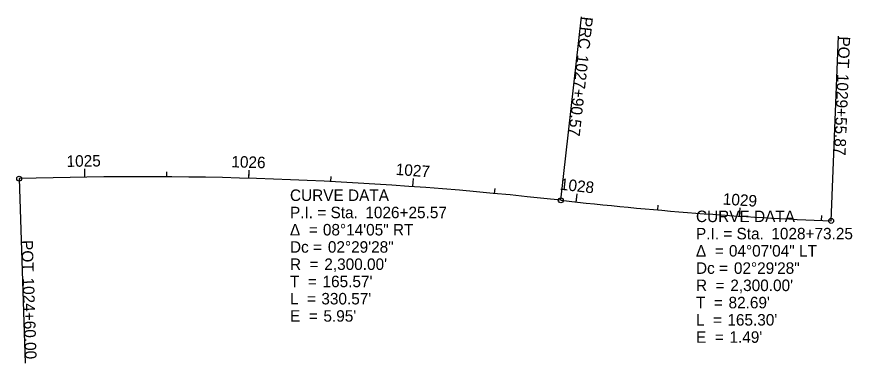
# Model space of a CAD drawing. Extents: x 2192966 to 2197975, y 660343 to 661858.
# Drawn here: x 2197466 to 2197975, y 661647 to 661858 of the extents above; entities that cross this region are included whole.
import ezdxf

# ---------------------------------------------------------------- set-up
doc = ezdxf.new("R2010")
doc.units = 0
for name, color, linetype in [('PM_X_Cells', 7, 'Continuous'), ('PM_X_CL_Double_Solid', 7, 'Continuous'), ('PM_X_Crosswalk', 7, 'Continuous'), ('PM_X_Dotted_Line', 7, 'Continuous'), ('PM_X_Edge_Line', 7, 'Continuous'), ('PM_X_Stop_Line', 7, 'Continuous'), ('PM_X_Yield_Line', 7, 'Continuous')]:
    doc.layers.add(name, color=color, linetype=linetype)

msp = doc.modelspace()

# ---------------------------------------------------------------- linework, layer by layer
at = {"layer": 'PM_X_Cells'}
for p, q in [((2197797.82, 661746.67), (2197810.38, 661858.46)), ((2197962.6, 661734.13), (2197967.1, 661846.54)), ((2197507.79, 661760.81), (2197507.74, 661763.81)), ((2197467.8, 661759.88), (2197471.38, 661647.44))]:
    msp.add_line(p, q, dxfattribs=at)
for centre in [(2197467.8, 661759.88), (2197797.82, 661746.67), (2197962.6, 661734.13)]:
    msp.add_circle(centre, 1.5, dxfattribs=at)
at = {"layer": 'PM_X_CL_Double_Solid'}
for p, q in [((2197797.82, 661746.67), (2197810.38, 661858.46)), ((2197962.6, 661734.13), (2197967.1, 661846.54)), ((2197507.79, 661760.81), (2197507.71, 661765.81)), ((2197607.78, 661760.08), (2197607.86, 661763.08)), ((2197467.8, 661759.88), (2197471.38, 661647.44)), ((2197707.64, 661755), (2197707.86, 661758)), ((2197807.19, 661745.63), (2197807.51, 661748.62)), ((2197906.81, 661737.04), (2197907.01, 661740.04))]:
    msp.add_line(p, q, dxfattribs=at)
for centre in [(2197467.8, 661759.88), (2197797.82, 661746.67), (2197962.6, 661734.13)]:
    msp.add_circle(centre, 1.5, dxfattribs=at)
at = {"layer": 'PM_X_Edge_Line'}
for centre, start, end in [((2197541.04, 659461.05), 83.58998, 91.82483), ((2198054.59, 664032.29), 263.58998, 267.7078)]:
    msp.add_arc(centre, 2300, start, end, dxfattribs=at)
at = {"layer": 'PM_X_Yield_Line'}
for p, q in [((2197797.82, 661746.67), (2197810.38, 661858.46)), ((2197962.6, 661734.13), (2197967.1, 661846.54)), ((2197507.79, 661760.81), (2197507.71, 661765.81)), ((2197557.78, 661760.99), (2197557.81, 661763.99)), ((2197607.78, 661760.08), (2197607.92, 661765.08)), ((2197657.73, 661758.08), (2197657.89, 661761.08)), ((2197467.8, 661759.88), (2197471.38, 661647.44)), ((2197707.64, 661755), (2197708, 661759.99)), ((2197757.46, 661750.84), (2197757.75, 661753.83)), ((2197807.19, 661745.63), (2197807.73, 661750.61)), ((2197856.96, 661740.8), (2197857.21, 661743.79)), ((2197906.81, 661737.04), (2197907.13, 661742.03)), ((2197956.74, 661734.37), (2197956.87, 661737.37))]:
    msp.add_line(p, q, dxfattribs=at)
for centre in [(2197467.8, 661759.88), (2197797.82, 661746.67), (2197962.6, 661734.13)]:
    msp.add_circle(centre, 1.5, dxfattribs=at)

# ---------------------------------------------------------------- texts
at = {"layer": 'PM_X_Cells'}
for s, rotation, p in [('PRC', 263.59, (2197810.53, 661858.79)), ('POT', 267.7078, (2197967.22, 661846.6)), ('1027+90.57', 263.59, (2197807.92, 661835.56)), ('1029+55.87', 267.7078, (2197966.31, 661823.79)), ('POT', 271.8248, (2197469.11, 661722.32)), ('1024+60.00', 271.8248, (2197469.84, 661699.51))]:
    msp.add_text(s, height=7, rotation=rotation, dxfattribs=at).set_placement(p)
at = {"layer": 'PM_X_CL_Double_Solid'}
for s, rotation, p in [('PRC', 263.59, (2197810.53, 661858.79)), ('POT', 267.7078, (2197967.22, 661846.6)), ('1027+90.57', 263.59, (2197807.92, 661835.56)), ('1029+55.87', 267.7078, (2197966.31, 661823.79)), ('1025', 0.8284, (2197496.74, 661767.01)), ('POT', 271.8248, (2197469.11, 661722.32)), ('1024+60.00', 271.8248, (2197469.84, 661699.51))]:
    msp.add_text(s, height=7, rotation=rotation, dxfattribs=at).set_placement(p)
at = {"layer": 'PM_X_Crosswalk'}
for s, p in [('CURVE DATA', (2197632.81, 661746.27)), ('P.I. = Sta. ', (2197632.81, 661735.77)), ('1026+25.57', (2197678.73, 661735.77)), ('CURVE DATA', (2197880.21, 661733.4)), ('Δ  = ', (2197632.81, 661725.27)), ('08°14\'05" RT', (2197652.86, 661725.27)), ('P.I. = Sta. ', (2197880.21, 661722.9)), ('1028+73.25', (2197926.13, 661722.9)), ('Dc = ', (2197632.81, 661714.77)), ('02°29\'28"', (2197655.9, 661714.77)), ('04°07\'04" LT', (2197900.27, 661712.4)), ('Δ  = ', (2197880.21, 661712.4)), ('R  = ', (2197632.81, 661704.27)), ("2,300.00'", (2197653.73, 661704.27)), ('Dc = ', (2197880.21, 661701.9)), ('02°29\'28"', (2197903.31, 661701.9)), ('T  = ', (2197632.81, 661693.77)), ("165.57'", (2197652.64, 661693.77)), ('R  = ', (2197880.21, 661691.4)), ("2,300.00'", (2197901.13, 661691.4)), ('L  = ', (2197632.81, 661683.27)), ("330.57'", (2197651.92, 661683.27)), ('T  = ', (2197880.21, 661680.9)), ("82.69'", (2197900.04, 661680.9)), ('E  = ', (2197632.81, 661672.77)), ("5.95'", (2197653.19, 661672.77)), ('L  = ', (2197880.21, 661670.4)), ("165.30'", (2197899.33, 661670.4)), ('E  = ', (2197880.21, 661659.9)), ("1.49'", (2197900.59, 661659.9))]:
    msp.add_text(s, height=7, dxfattribs=at).set_placement(p)
at = {"layer": 'PM_X_Dotted_Line'}
for s, p in [('CURVE DATA', (2197632.81, 661746.27)), ('P.I. = Sta. ', (2197632.81, 661735.77)), ('1026+25.57', (2197678.73, 661735.77)), ('CURVE DATA', (2197880.21, 661733.4)), ('Δ  = ', (2197632.81, 661725.27)), ('08°14\'05" RT', (2197652.86, 661725.27)), ('P.I. = Sta. ', (2197880.21, 661722.9)), ('1028+73.25', (2197926.13, 661722.9)), ('Dc = ', (2197632.81, 661714.77)), ('02°29\'28"', (2197655.9, 661714.77)), ('04°07\'04" LT', (2197900.27, 661712.4)), ('Δ  = ', (2197880.21, 661712.4)), ('R  = ', (2197632.81, 661704.27)), ("2,300.00'", (2197653.73, 661704.27)), ('Dc = ', (2197880.21, 661701.9)), ('02°29\'28"', (2197903.31, 661701.9)), ('T  = ', (2197632.81, 661693.77)), ("165.57'", (2197652.64, 661693.77)), ('R  = ', (2197880.21, 661691.4)), ("2,300.00'", (2197901.13, 661691.4)), ('L  = ', (2197632.81, 661683.27)), ("330.57'", (2197651.92, 661683.27)), ('T  = ', (2197880.21, 661680.9)), ("82.69'", (2197900.04, 661680.9)), ('E  = ', (2197632.81, 661672.77)), ("5.95'", (2197653.19, 661672.77)), ('L  = ', (2197880.21, 661670.4)), ("165.30'", (2197899.33, 661670.4)), ('E  = ', (2197880.21, 661659.9)), ("1.49'", (2197900.59, 661659.9))]:
    msp.add_text(s, height=7, dxfattribs=at).set_placement(p)
at = {"layer": 'PM_X_Stop_Line'}
for s, p in [('CURVE DATA', (2197632.81, 661746.27)), ('P.I. = Sta. ', (2197632.81, 661735.77)), ('1026+25.57', (2197678.73, 661735.77)), ('CURVE DATA', (2197880.21, 661733.4)), ('Δ  = ', (2197632.81, 661725.27)), ('08°14\'05" RT', (2197652.86, 661725.27)), ('P.I. = Sta. ', (2197880.21, 661722.9)), ('1028+73.25', (2197926.13, 661722.9)), ('Dc = ', (2197632.81, 661714.77)), ('02°29\'28"', (2197655.9, 661714.77)), ('04°07\'04" LT', (2197900.27, 661712.4)), ('Δ  = ', (2197880.21, 661712.4)), ('R  = ', (2197632.81, 661704.27)), ("2,300.00'", (2197653.73, 661704.27)), ('Dc = ', (2197880.21, 661701.9)), ('02°29\'28"', (2197903.31, 661701.9)), ('T  = ', (2197632.81, 661693.77)), ("165.57'", (2197652.64, 661693.77)), ('R  = ', (2197880.21, 661691.4)), ("2,300.00'", (2197901.13, 661691.4)), ('L  = ', (2197632.81, 661683.27)), ("330.57'", (2197651.92, 661683.27)), ('T  = ', (2197880.21, 661680.9)), ("82.69'", (2197900.04, 661680.9)), ('E  = ', (2197632.81, 661672.77)), ("5.95'", (2197653.19, 661672.77)), ('L  = ', (2197880.21, 661670.4)), ("165.30'", (2197899.33, 661670.4)), ('E  = ', (2197880.21, 661659.9)), ("1.49'", (2197900.59, 661659.9))]:
    msp.add_text(s, height=7, dxfattribs=at).set_placement(p)
at = {"layer": 'PM_X_Yield_Line'}
for s, rotation, p in [('PRC', 263.59, (2197810.53, 661858.79)), ('POT', 267.7078, (2197967.22, 661846.6)), ('1027+90.57', 263.59, (2197807.92, 661835.56)), ('1029+55.87', 267.7078, (2197966.31, 661823.79)), ('1025', 0.8284, (2197496.74, 661767.01)), ('1026', 358.3373, (2197597.03, 661766.76)), ('1027', 355.8461, (2197697.06, 661762.16)), ('1028', 353.825, (2197797.03, 661753.14)), ('1029', 356.3161, (2197896.4, 661744.09)), ('POT', 271.8248, (2197469.11, 661722.32)), ('1024+60.00', 271.8248, (2197469.84, 661699.51))]:
    msp.add_text(s, height=7, rotation=rotation, dxfattribs=at).set_placement(p)

doc.saveas('drawing.dxf')
